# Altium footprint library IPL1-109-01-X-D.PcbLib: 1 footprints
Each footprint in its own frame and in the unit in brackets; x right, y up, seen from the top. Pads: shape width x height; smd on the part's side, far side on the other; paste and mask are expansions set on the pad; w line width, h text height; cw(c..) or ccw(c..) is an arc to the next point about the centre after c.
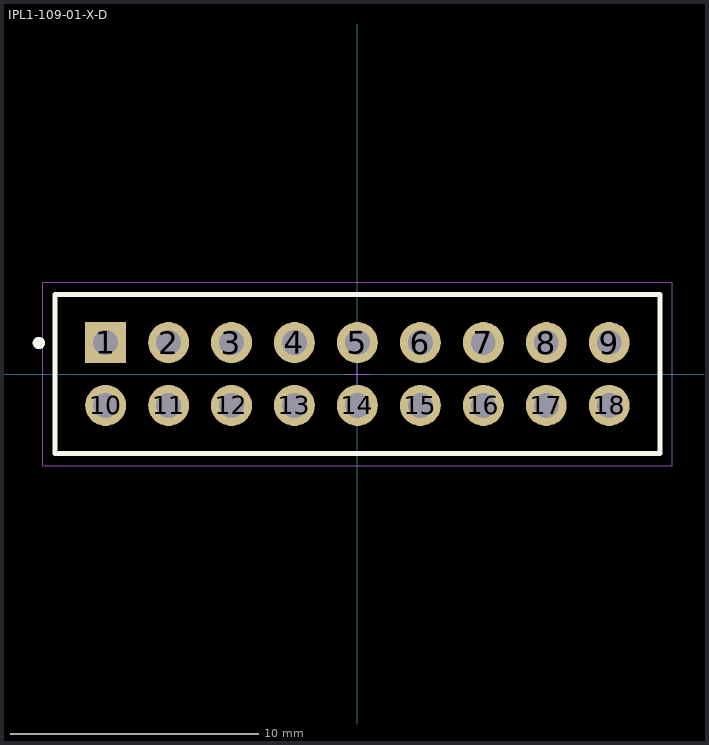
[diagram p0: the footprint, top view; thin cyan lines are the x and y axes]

## IPL1-109-01-X-D [mm] "2.54mm pitch, isolated power locking header"
height 8.13
pads (18):
  rect 1.65x1.65 / inner round 1.65 / far side rect 1.65x1.65 hole 1 mask+0: 1(-10.16,1.27)
  round 1.65 hole 1 mask+0: 2(-7.62,1.27) 3(-5.08,1.27) 4(-2.54,1.27) 5(0,1.27) 6(2.54,1.27) 7(5.08,1.27) 8(7.62,1.27) 9(10.16,1.27) 10(-10.16,-1.27) 11(-7.62,-1.27) 12(-5.08,-1.27) 13(-2.54,-1.27) 14(0,-1.27) 15(2.54,-1.27) 16(5.08,-1.27) 17(7.62,-1.27) 18(10.16,-1.27)
Top Overlay:
  circle w0.25: c-12.85,1.25 r0.125
  lines w0.2: -12.2,-3.2 12.2,-3.2 12.2,3.2 -12.2,3.2 -12.2,-3.2
Mechanical 12:
  lines w0.001: -12.2,-3.2 12.2,-3.2 12.2,3.2 -12.2,3.2 -12.2,-3.2
Mechanical 13:
  lines w0.1: -12.2,-3.2 12.2,-3.2 12.2,3.2 -12.2,3.2 -12.2,-3.2
  text ".Designator" at 0.254,0.254 h1.52
Mechanical 15:
  lines w0.05: -0.5,0 0.5,0 ; 0,-0.5 0,0.5 ; -12.7,-3.7 12.7,-3.7 12.7,3.7 -12.7,3.7 -12.7,-3.7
